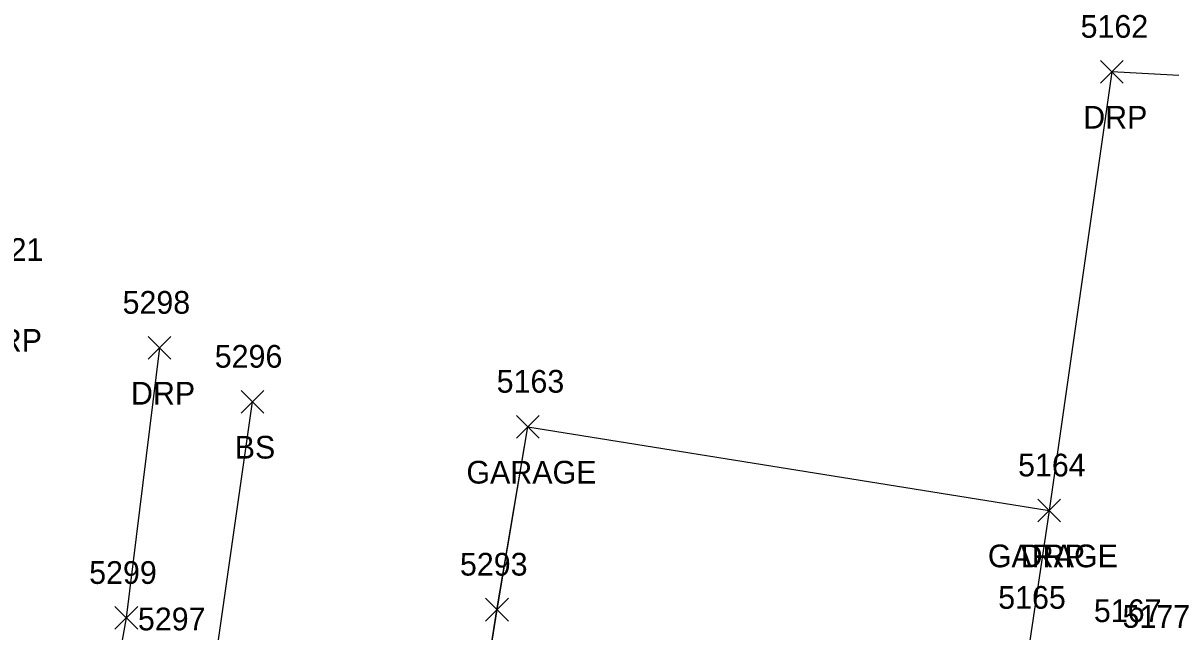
# Model space of a CAD drawing. Extents: x 1554668 to 1563881, y 831386 to 834374.
# Drawn here: x 1562135.6 to 1562236.5, y 833103 to 833156.6 of the extents above; entities that cross this region are included whole.
import ezdxf

# ---------------------------------------------------------------- set-up
doc = ezdxf.new("R2010")
doc.units = 0
for name, color, linetype in [('L_A', 7, 'Continuous'), ('L_I', 7, 'Continuous'), ('L_TIC', 7, 'Continuous'), ('LBC', 7, 'Continuous'), ('LELB', 7, 'Continuous'), ('R_A', 7, 'Continuous'), ('R_I', 7, 'Continuous'), ('R_TIC', 7, 'Continuous'), ('RDP', 7, 'Continuous')]:
    doc.layers.add(name, color=color, linetype=linetype)

msp = doc.modelspace()

# ---------------------------------------------------------------- linework, layer by layer
at = {"layer": 'L_TIC'}
for points in [[(1562154.75, 833122.23), (1562156.75, 833124.23)], [(1562156.75, 833122.23), (1562154.75, 833124.23)], [(1562178.98, 833120.03), (1562180.98, 833122.03)], [(1562180.98, 833120.03), (1562178.98, 833122.03)], [(1562224.87, 833112.66), (1562226.87, 833114.66)], [(1562226.87, 833112.66), (1562224.87, 833114.66)], [(1562176.27, 833103.93), (1562178.27, 833105.93)], [(1562178.27, 833103.93), (1562176.27, 833105.93)]]:
    msp.add_lwpolyline(points, dxfattribs=at)
at = {"layer": 'LBC'}
for points in [[(1562177.27, 833104.93), (1562179.98, 833121.03)], [(1562177.28, 833104.93), (1562179.99, 833121.03)], [(1562177.28, 833104.93), (1562179.99, 833121.03)], [(1562177.28, 833104.93), (1562179.99, 833121.03)], [(1562179.98, 833121.03), (1562225.87, 833113.66), (1562224.13, 833102.01), (1562223.41, 833097.54)], [(1562179.99, 833121.03), (1562225.87, 833113.66), (1562224.13, 833102.01), (1562223.42, 833097.54)], [(1562179.99, 833121.03), (1562225.87, 833113.66), (1562224.13, 833102.01), (1562223.42, 833097.54)], [(1562179.99, 833121.03), (1562225.87, 833113.66), (1562224.13, 833102.01), (1562223.42, 833097.54)], [(1562223.42, 833097.54), (1562218.69, 833068.29), (1562217.95, 833063.49), (1562196.42, 833066.9), (1562193.25, 833067.4), (1562171.81, 833070.93), (1562174.9, 833089.92), (1562175.84, 833095.92), (1562177.28, 833104.93)], [(1562223.42, 833097.54), (1562218.69, 833068.29), (1562217.95, 833063.49), (1562196.42, 833066.9), (1562193.25, 833067.4), (1562171.81, 833070.93), (1562174.9, 833089.92), (1562175.84, 833095.92), (1562177.28, 833104.93)], [(1562223.42, 833097.54), (1562218.69, 833068.29), (1562217.95, 833063.49), (1562196.42, 833066.9), (1562193.25, 833067.4), (1562171.81, 833070.93), (1562174.9, 833089.92), (1562175.84, 833095.92), (1562177.28, 833104.93)], [(1562223.41, 833097.54), (1562218.69, 833068.29), (1562217.95, 833063.49), (1562196.42, 833066.9), (1562193.24, 833067.39), (1562171.81, 833070.93), (1562174.9, 833089.92), (1562175.84, 833095.92), (1562177.27, 833104.93)]]:
    msp.add_lwpolyline(points, dxfattribs=at)
at = {"layer": 'LELB'}
for points in [[(1562155.55, 833055.47), (1562148.1, 833066.28), (1562150.33, 833085.23), (1562155.75, 833123.23)], [(1562155.55, 833055.48), (1562148.1, 833066.27), (1562150.33, 833085.23), (1562155.75, 833123.22)], [(1562155.55, 833055.48), (1562148.1, 833066.27), (1562150.33, 833085.23), (1562155.75, 833123.22)], [(1562155.55, 833055.48), (1562148.1, 833066.27), (1562150.33, 833085.23), (1562155.75, 833123.22)]]:
    msp.add_lwpolyline(points, dxfattribs=at)
at = {"layer": 'R_TIC'}
for points in [[(1562230.37, 833151.27), (1562232.37, 833153.27)], [(1562232.37, 833151.27), (1562230.37, 833153.27)], [(1562146.58, 833126.98), (1562148.58, 833128.98)], [(1562148.58, 833126.98), (1562146.58, 833128.98)], [(1562224.87, 833112.66), (1562226.87, 833114.66)], [(1562226.87, 833112.66), (1562224.87, 833114.66)], [(1562143.65, 833103.2), (1562145.65, 833105.2)], [(1562145.65, 833103.2), (1562143.65, 833105.2)]]:
    msp.add_lwpolyline(points, dxfattribs=at)
at = {"layer": 'RDP'}
for points in [[(1562244.8, 833151.54), (1562231.37, 833152.27), (1562225.87, 833113.66)], [(1562244.8, 833151.54), (1562231.37, 833152.27), (1562225.87, 833113.66)], [(1562244.8, 833151.54), (1562231.37, 833152.27), (1562225.87, 833113.66)], [(1562244.79, 833151.54), (1562231.37, 833152.27), (1562225.87, 833113.66)], [(1562147.58, 833127.98), (1562144.65, 833104.2), (1562139.18, 833073.74), (1562137.13, 833060.4), (1562138.16, 833053.34), (1562141.25, 833047.12)], [(1562147.58, 833127.98), (1562144.65, 833104.2), (1562139.18, 833073.74), (1562137.13, 833060.4), (1562138.16, 833053.34), (1562141.25, 833047.12)], [(1562147.58, 833127.98), (1562144.65, 833104.2), (1562139.18, 833073.74), (1562137.13, 833060.4), (1562138.16, 833053.34), (1562141.25, 833047.12)], [(1562147.58, 833127.98), (1562144.65, 833104.2), (1562139.18, 833073.74), (1562137.13, 833060.41), (1562138.15, 833053.34), (1562141.25, 833047.12)]]:
    msp.add_lwpolyline(points, dxfattribs=at)

# ---------------------------------------------------------------- texts
at = {"layer": 'L_A'}
for s, p in [('BS', (1562154.19, 833118.23)), ('GARAGE', (1562174.58, 833116.03)), ('GARAGE', (1562220.47, 833108.66))]:
    msp.add_text(s, height=2, dxfattribs=at).set_placement(p)
at = {"layer": 'L_I'}
for s, p in [('5296', (1562152.43, 833126.23)), ('5163', (1562177.24, 833124.03)), ('5164', (1562223.13, 833116.66)), ('5293', (1562174.01, 833107.93)), ('5165', (1562221.38, 833105.01)), ('5297', (1562145.67, 833103.11))]:
    msp.add_text(s, height=2, dxfattribs=at).set_placement(p)
at = {"layer": 'R_A'}
for p in [(1562228.86, 833147.27), (1562131.58, 833127.63), (1562145.06, 833122.98), (1562223.36, 833108.66)]:
    msp.add_text('DRP', height=2, dxfattribs=at).set_placement(p)
at = {"layer": 'R_I'}
for s, p in [('5162', (1562228.63, 833155.27)), ('5321', (1562131.4, 833135.63)), ('5298', (1562144.32, 833130.98)), ('5164', (1562223.13, 833116.66)), ('5299', (1562141.38, 833107.2)), ('5165', (1562221.38, 833105.01)), ('5167', (1562229.8, 833103.84)), ('5167', (1562229.8, 833103.84)), ('5177', (1562232.32, 833103.33)), ('5177', (1562232.32, 833103.33))]:
    msp.add_text(s, height=2, dxfattribs=at).set_placement(p)

doc.saveas('drawing.dxf')
